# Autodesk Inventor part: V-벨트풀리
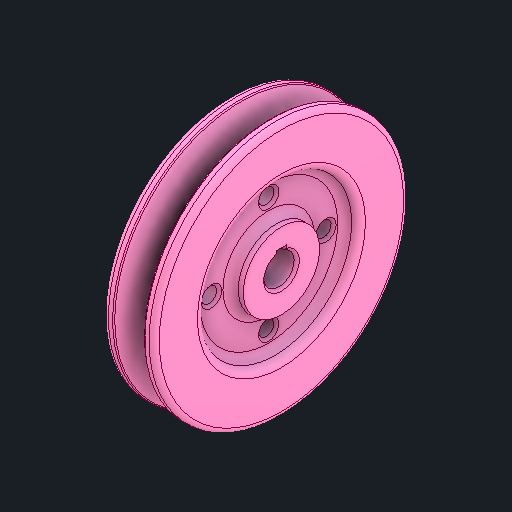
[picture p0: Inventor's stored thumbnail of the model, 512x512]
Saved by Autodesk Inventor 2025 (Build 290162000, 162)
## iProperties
Created: 2025-08
Part Number: V-벨트풀리
Material: 강철, 연강
Document SubType Name: Modeling
Designer: infra002
Density: 7.86 g/cm^3
Appearance: 기본값
Author: jhkim
Sending System: Autodesk Inventor 2026
Preprocessor: ST-DEVELOPER v20.1
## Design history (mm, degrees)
feature "솔리드1"
node "솔리드2"
